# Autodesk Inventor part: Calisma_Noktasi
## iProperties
Company: Autodesk, Inc.
Shininess: 64.0
Length Units: 11269
Angle Units: 11279
Time Units: 11290
Mass Units: 11283
Length Display Precision: 3
Angle Display Precision: 2
Compacted: True
Part Number: Calisma_Noktasi
Document SubType Name: Modeling
Created: 2003-11
Catalog Web Link: www.autodesk.com
Vendor: Autodesk, Inc.
Designer: Administrator
Manufacturer: Standard
Standards Organization: Custom
Density: 1 g/cm^3
Density: 0.0
Volumn: 0.0
Area: 0.0
PropertySet Name: Model Information
Control State: 0
Master: False
Checked Out: False
Author: Administrator
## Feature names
1. Extrusion1
